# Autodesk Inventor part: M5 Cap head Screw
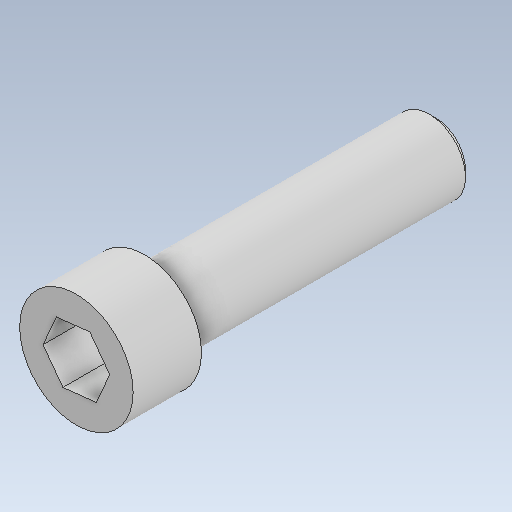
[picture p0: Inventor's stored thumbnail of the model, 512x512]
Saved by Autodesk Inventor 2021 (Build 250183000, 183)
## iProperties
Created: 2023-10
Part Number: M5 Cap head Screw
Material: Generico
Document SubType Name: Modeling
Designer: hp
Density: 1 g/cm^3
Appearance: Default
Author: hp
Revision Number: ANY
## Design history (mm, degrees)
feature "Solido1"
body "Solid1"
